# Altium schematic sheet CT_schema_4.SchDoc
size 357 x 214 mm
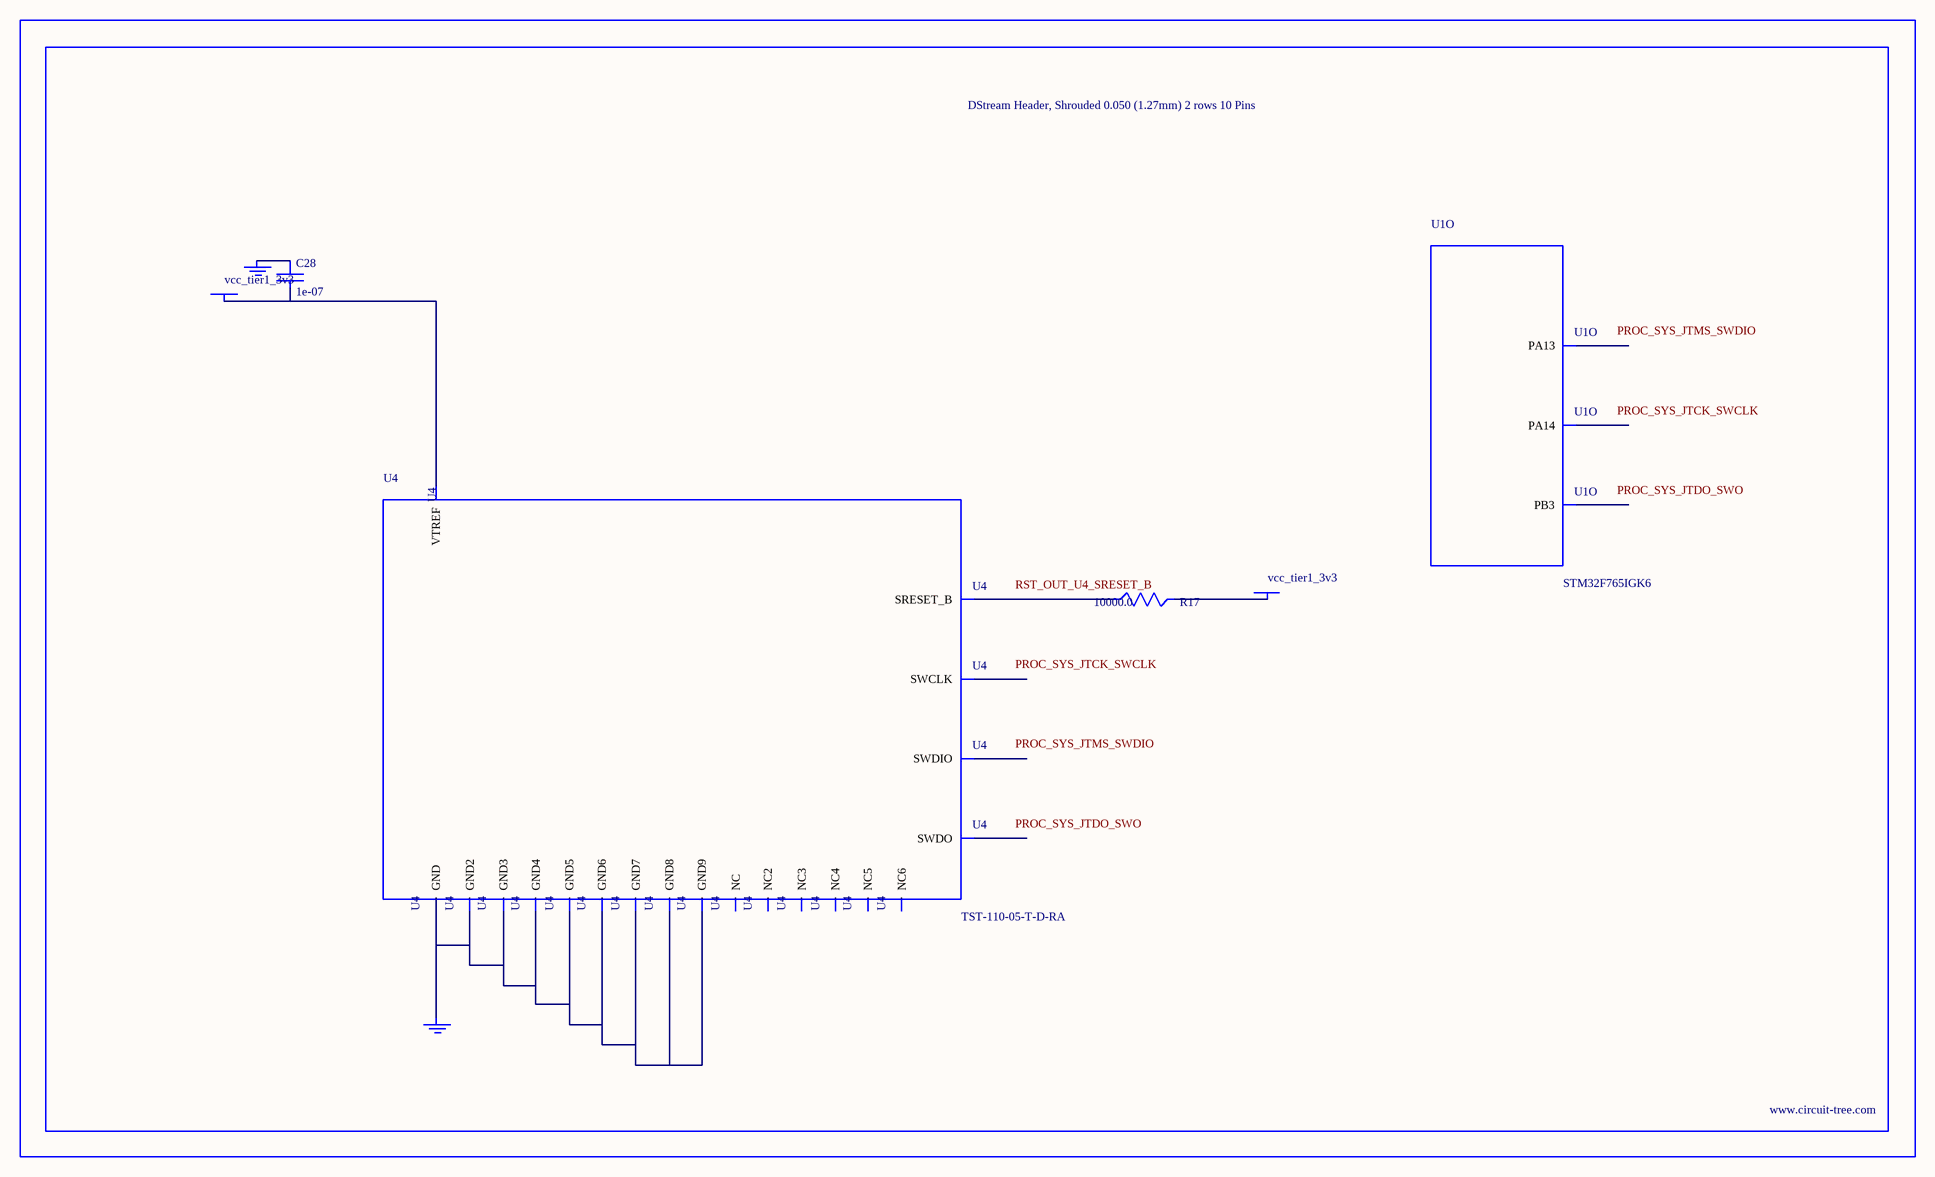
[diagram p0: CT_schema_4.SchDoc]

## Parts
BORDER3  (no value)
C28  1e-07  [C0402]
GND_INSTANCE_3_0  (no value)
GND_INSTANCE_3_1  (no value)
POWER_INSTANCE_3_0  vcc_tier1_3v3
POWER_INSTANCE_3_1  vcc_tier1_3v3
R17  10000.0  [R0603]
U1  STM32F765IGK6  [UFBGA176_25]  (part O of 17)
U4  TST-110-05-T-D-RA  [TST-110-05-T-D-RA]

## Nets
NetC28_1: C28.1 GND_INSTANCE_3_0.0(GND)
NetC28_2: C28.2 POWER_INSTANCE_3_0.0(PWR) U4.1(VTREF)
NetGND_INSTANCE_3_1_0: GND_INSTANCE_3_1.0(GND) U4.4(GND) U4.6(GND2) U4.8(GND3) U4.10(GND4) U4.12(GND5) U4.14(GND6) U4.16(GND7) U4.18(GND8) U4.20(GND9)
NetPOWER_INSTANCE_3_1_0: POWER_INSTANCE_3_1.0(PWR) R17.2
NetR17_1: R17.1 U4.15(SRESET_B)

Not connected (* = marked no-connect by the designer): U1 A10(PB3) A14(PA14) A15(PA13); U4 2(NC) 3(NC2) 5(NC3) 7(SWDIO) 9(SWCLK) 11(NC4) 13(SWDO) 17(NC5) 19(NC6)

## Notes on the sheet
- Labels drawn without touching a wire or pin: PROC_SYS_JTCK_SWCLK, PROC_SYS_JTDO_SWO, PROC_SYS_JTMS_SWDIO, RST_OUT_U4_SRESET_B

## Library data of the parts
BORDER3 = BORDER_PAGE3
C28 = C0402C104K3RACTU
GND_INSTANCE_3_0 GND_INSTANCE_3_1 = GND
POWER_INSTANCE_3_0 POWER_INSTANCE_3_1 = PWR
R17 = RC0603JR-0710KL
